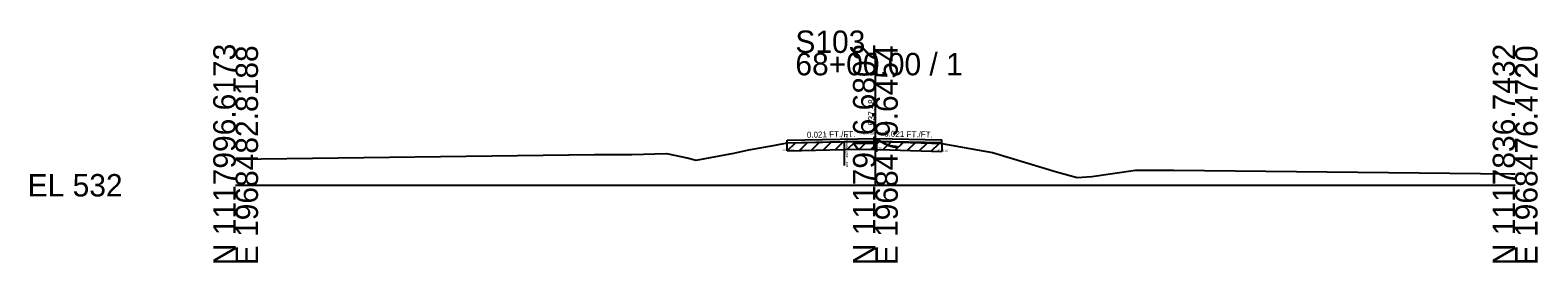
# Model space of a CAD drawing. Extents: x -26 to 163, y -10 to 24018.
# Drawn here: x -25.7 to 162.8, y 15990.3 to 16019.4 of the extents above; entities that cross this region are included whole.
import ezdxf

# ---------------------------------------------------------------- set-up
doc = ezdxf.new("R2010")
doc.units = 0
for name, color, linetype in [('RD_GPK_XS_Cell', 7, 'Continuous'), ('RD_XS_ExGround', 7, 'Continuous'), ('RD_XS_ExPaveRet', 7, 'Continuous'), ('RD_XS_Misc_Line', 7, 'Continuous'), ('RD_XS_PaveOvlay_CP', 7, 'Continuous'), ('RD_XS_TX_Elev_EX', 7, 'Continuous'), ('RD_XS_TX_ExEOP', 7, 'Continuous'), ('RD_XS_TX_Notes', 7, 'Continuous'), ('RD_XS_TX_Profile', 7, 'Continuous'), ('RD_XS_TX_Slope', 7, 'Continuous')]:
    doc.layers.add(name, color=color, linetype=linetype)

msp = doc.modelspace()

# ---------------------------------------------------------------- linework, layer by layer
at = {"layer": 'RD_GPK_XS_Cell'}
for p, q in [((80, 16000), (80, 16016.54)), ((0, 16000), (80, 16000)), ((80, 16000), (160, 16000))]:
    msp.add_line(p, q, dxfattribs=at)
at = {"layer": 'RD_XS_ExGround'}
msp.add_lwpolyline([(0, 16003.27), (44.87, 16003.84), (49.53, 16003.83), (53.88, 16003.99), (56.48, 16003.42), (57.59, 16003.13), (62.3, 16004.03), (64.18, 16004.41), (67.47, 16005.03), (68.99, 16005.29), (76.08, 16005.45), (78.94, 16005.51), (80, 16005.48), (81.79, 16005.42), (88.3, 16005.2), (92.96, 16004.38), (94.63, 16004.09), (102.66, 16001.66), (105.25, 16000.96), (107.06, 16001.11), (112.53, 16001.9), (117.34, 16001.89), (159.52, 16001.41), (160, 16001.41)], dxfattribs=at)
at = {"layer": 'RD_XS_ExPaveRet'}
for p, q in [((68.99, 16004.29), (70.02, 16005.31)), ((68.99, 16004.29), (68.99, 16005.29)), ((70.49, 16004.32), (71.52, 16005.35)), ((71.99, 16004.36), (73.02, 16005.38)), ((73.49, 16004.39), (74.52, 16005.42)), ((74.99, 16004.43), (76.02, 16005.45)), ((76.49, 16004.46), (77.51, 16005.48)), ((77.99, 16004.49), (79.01, 16005.51)), ((79.49, 16004.5), (80.46, 16005.46)), ((80.99, 16004.45), (81.96, 16005.41)), ((82.49, 16004.4), (83.46, 16005.36)), ((83.99, 16004.35), (84.96, 16005.31)), ((85.49, 16004.3), (86.46, 16005.26)), ((86.99, 16004.25), (87.96, 16005.22)), ((88.3, 16005.2), (88.3, 16004.2)), ((68.99, 16004.29), (76.08, 16004.45)), ((76.08, 16004.45), (78.94, 16004.51)), ((78.94, 16004.51), (80, 16004.48)), ((80, 16004.48), (81.79, 16004.42)), ((81.79, 16004.42), (88.3, 16004.2))]:
    msp.add_line(p, q, dxfattribs=at)
at = {"layer": 'RD_XS_Misc_Line'}
msp.add_line((76.08, 16005.45), (76.08, 16002.45), dxfattribs=at)
at = {"layer": 'RD_XS_PaveOvlay_CP'}
for p, q in [((68.99, 16005.63), (80, 16005.86)), ((68.99, 16005.29), (68.99, 16005.63)), ((80, 16005.48), (68.99, 16005.25)), ((80, 16005.86), (88.3, 16005.68)), ((88.3, 16005.31), (80, 16005.48)), ((88.3, 16005.2), (88.3, 16005.68))]:
    msp.add_line(p, q, dxfattribs=at)

# ---------------------------------------------------------------- texts
at = {"layer": 'RD_GPK_XS_Cell'}
for s, p in [('S103', (70, 16016.54)), ('68+00.00 / 1', (70, 16013.74)), ('EL 532', (-26, 15998.6))]:
    msp.add_text(s, height=2.8, dxfattribs=at).set_placement(p)
for s, p in [('N 1117996.6173', (0, 15990)), ('E 1968482.8188', (2.8, 15990)), ('N 1117916.6802', (80, 15990)), ('E 1968479.6454', (82.8, 15990)), ('N 1117836.7432', (160, 15990)), ('E 1968476.4720', (162.8, 15990))]:
    msp.add_text(s, height=2.8, rotation=90, dxfattribs=at).set_placement(p)
at = {"layer": 'RD_XS_TX_Elev_EX'}
msp.add_text('537.48', height=0.8, rotation=90, dxfattribs=at).set_placement((79.9, 16007.48))
at = {"layer": 'RD_XS_TX_ExEOP'}
for s, p in [('EOP-L', (68.94, 16005.63)), ('EOP-R', (88.25, 16005.68))]:
    msp.add_text(s, height=0.1, rotation=270, dxfattribs=at).set_placement(p)
at = {"layer": 'RD_XS_TX_Notes'}
msp.add_text(' Min. Distance @CP = -0.06', height=0.25, rotation=270, dxfattribs=at).set_placement((76.33, 16006.55))
for s, p in [('Elev. @CL = 537.86', (78.47, 16006.36)), (' dE= 0.34', (68.28, 16004.29)), (' dE= 0.38', (79.29, 16004.48)), (' dE= 0.48', (87.59, 16004.2))]:
    msp.add_text(s, height=0.25, dxfattribs=at).set_placement(p)
at = {"layer": 'RD_XS_TX_Profile'}
msp.add_text('CL', height=0.25, dxfattribs=at).set_placement((79.77, 16005.86))
at = {"layer": 'RD_XS_TX_Slope'}
for rotation, p in [(1.1916, (71.44, 16005.93)), (358.8084, (81.1, 16006.08))]:
    msp.add_text('0.021 FT./FT.', height=0.75, rotation=rotation, dxfattribs=at).set_placement(p)

doc.saveas('drawing.dxf')
